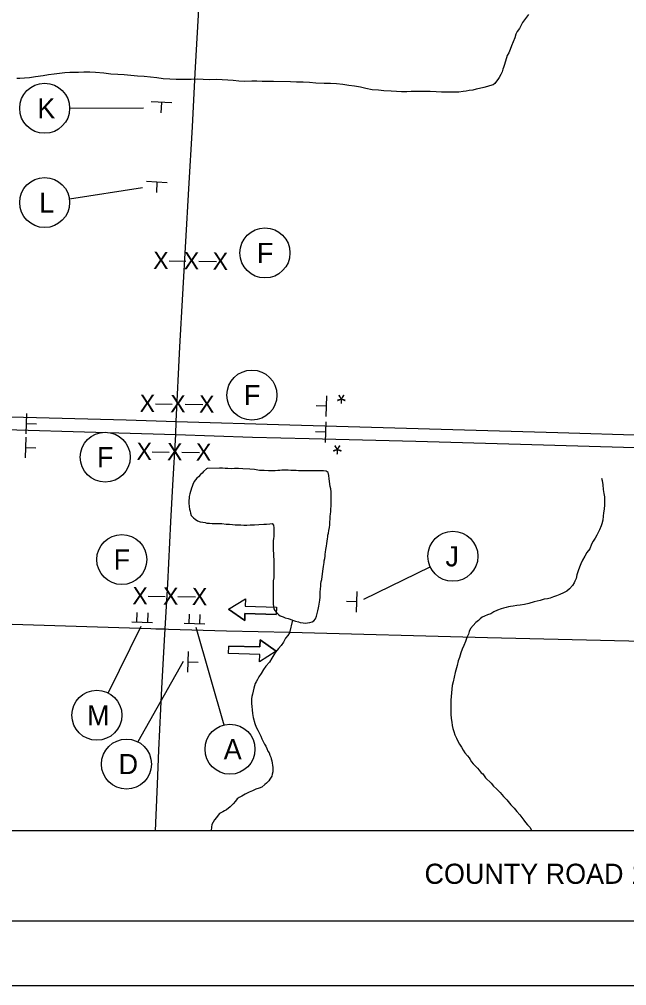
# Model space of a CAD drawing. Extents: x 1651.5 to 1685.5, y 1084.6 to 1106.6.
# Drawn here: x 1656.25 to 1660.95, y 1084.6 to 1092.09 of the extents above; entities that cross this region are included whole.
import ezdxf

# ---------------------------------------------------------------- set-up
doc = ezdxf.new("R2010")
doc.units = 0
for name, color, linetype in [('GM_X_County_Road', 7, 'Continuous'), ('GM_X_Minor_Lake', 7, 'Continuous'), ('GM_X_Minor_River', 7, 'Continuous'), ('GM_X_State_Route', 7, 'Continuous'), ('GM_X_Township_Road', 7, 'Continuous'), ('SC_Scratch1', 7, 'Continuous'), ('SH_Border', 7, 'Continuous'), ('SH_Data', 7, 'Continuous'), ('SH_Text', 7, 'Continuous'), ('SN_P_Signs', 7, 'Continuous'), ('SN_X_Public', 7, 'Continuous')]:
    doc.layers.add(name, color=color, linetype=linetype)

msp = doc.modelspace()

# ---------------------------------------------------------------- linework, layer by layer
at = {"layer": 'GM_X_County_Road'}
for points in [[(1657.4657, 1088.9713), (1657.4943, 1089.549), (1657.5621, 1090.7723), (1657.5909, 1091.2527), (1657.6123, 1091.6678), (1657.6464, 1092.2577), (1657.6502, 1092.3049), (1657.6569, 1092.3768), (1657.6601, 1092.4109)], [(1657.4608, 1088.8688), (1657.4657, 1088.9713)], [(1657.379, 1087.3642), (1657.3992, 1087.7139), (1657.4244, 1088.1945), (1657.439, 1088.4787), (1657.4608, 1088.8688)], [(1653.9882, 1087.4595), (1654.4044, 1087.4528), (1655.323, 1087.4263), (1656.1102, 1087.4042), (1657.2691, 1087.3668), (1657.3069, 1087.3659), (1657.379, 1087.3642)], [(1657.379, 1087.3642), (1657.4053, 1087.3633), (1657.8544, 1087.3482), (1658.3449, 1087.3387), (1659.8761, 1087.2977), (1661.0794, 1087.2696), (1662.2169, 1087.2377), (1663.5074, 1087.1976), (1664.3823, 1087.1736), (1664.5355, 1087.1696)]]:
    msp.add_lwpolyline(points, dxfattribs=at)
at = {"layer": 'GM_X_Minor_Lake'}
for points in [[(1657.7041, 1088.6067), (1657.7003, 1088.6046), (1657.6761, 1088.5832), (1657.6654, 1088.5699), (1657.652, 1088.5592), (1657.6386, 1088.5432), (1657.6252, 1088.5326), (1657.6037, 1088.5059), (1657.5929, 1088.4818), (1657.5876, 1088.4685), (1657.5822, 1088.4551), (1657.5714, 1088.4097), (1657.566, 1088.391), (1657.5659, 1088.3776), (1657.5632, 1088.3589), (1657.5632, 1088.3375), (1657.5658, 1088.3134), (1657.5684, 1088.292), (1657.5737, 1088.2759), (1657.5764, 1088.2598), (1657.5817, 1088.2437), (1657.5977, 1088.225), (1657.6111, 1088.2142), (1657.6298, 1088.2008), (1657.6511, 1088.1927), (1657.6725, 1088.19), (1657.6886, 1088.1872), (1657.702, 1088.1845), (1657.7234, 1088.1845), (1657.7448, 1088.1817), (1657.7689, 1088.1816), (1657.7929, 1088.1815), (1657.8197, 1088.1815), (1657.8518, 1088.176), (1657.8785, 1088.1759), (1657.8999, 1088.1732), (1657.9213, 1088.1704), (1657.9454, 1088.1704), (1657.9668, 1088.1703), (1657.9882, 1088.1675), (1658.0123, 1088.1675), (1658.0391, 1088.1701), (1658.0712, 1088.1699), (1658.106, 1088.1725), (1658.1434, 1088.1751), (1658.1649, 1088.175), (1658.1916, 1088.1776), (1658.2077, 1088.1802), (1658.2183, 1088.1668), (1658.221, 1088.1481), (1658.2209, 1088.132), (1658.2209, 1088.1106), (1658.2209, 1088.0972), (1658.2208, 1088.0812), (1658.2181, 1088.0651), (1658.2154, 1088.0464), (1658.2153, 1088.0277), (1658.2153, 1088.0143), (1658.2153, 1087.9983), (1658.2152, 1087.9822), (1658.2152, 1087.9688), (1658.2178, 1087.9501), (1658.2178, 1087.926), (1658.2204, 1087.9019), (1658.2204, 1087.8779), (1658.2203, 1087.8591), (1658.2203, 1087.8431), (1658.2202, 1087.8217), (1658.2202, 1087.8029), (1658.2201, 1087.7842), (1658.2201, 1087.7601), (1658.2173, 1087.7361), (1658.2173, 1087.712), (1658.2172, 1087.6879), (1658.2172, 1087.6692), (1658.2171, 1087.6505), (1658.2171, 1087.6291), (1658.2171, 1087.613), (1658.217, 1087.5969), (1658.217, 1087.5782), (1658.2169, 1087.5595), (1658.2196, 1087.5354), (1658.2222, 1087.5193), (1658.2302, 1087.5059), (1658.2409, 1087.4925), (1658.2569, 1087.4764), (1658.2703, 1087.4657), (1658.2943, 1087.4576), (1658.3103, 1087.4495), (1658.3317, 1087.4441), (1658.3478, 1087.4387), (1658.3665, 1087.4306), (1658.3879, 1087.4252), (1658.412, 1087.4197), (1658.4253, 1087.4143), (1658.4494, 1087.4116), (1658.4628, 1087.4089), (1658.4815, 1087.4115), (1658.5003, 1087.4141), (1658.519, 1087.4194)], [(1658.519, 1087.4194), (1658.5324, 1087.4274), (1658.5431, 1087.4434), (1658.5512, 1087.4621), (1658.5566, 1087.4835), (1658.562, 1087.5049), (1658.5674, 1087.5263), (1658.5701, 1087.5396), (1658.5728, 1087.5557), (1658.5782, 1087.5878), (1658.581, 1087.6092), (1658.581, 1087.6279), (1658.5811, 1087.6493), (1658.5838, 1087.6734), (1658.5865, 1087.6948), (1658.5866, 1087.7135), (1658.5893, 1087.7322), (1658.592, 1087.7456), (1658.5947, 1087.7697), (1658.6029, 1087.8285), (1658.6056, 1087.8472), (1658.6083, 1087.8632), (1658.611, 1087.8793), (1658.6111, 1087.8927), (1658.6164, 1087.9087), (1658.6192, 1087.9274), (1658.6192, 1087.9435), (1658.6219, 1087.9595), (1658.6246, 1087.9782), (1658.63, 1088.005), (1658.6328, 1088.0264), (1658.6355, 1088.0451), (1658.6382, 1088.0611), (1658.6409, 1088.0772), (1658.6409, 1088.0906), (1658.6437, 1088.1066), (1658.6464, 1088.1253), (1658.6518, 1088.1494), (1658.6545, 1088.1708), (1658.6545, 1088.1922), (1658.6573, 1088.2162), (1658.6573, 1088.2377), (1658.66, 1088.2537), (1658.6628, 1088.2724), (1658.6628, 1088.2938), (1658.6655, 1088.3152), (1658.6656, 1088.3366), (1658.6656, 1088.3553), (1658.6657, 1088.3741), (1658.6657, 1088.3928), (1658.6657, 1088.4089), (1658.6658, 1088.4249), (1658.6632, 1088.449), (1658.6579, 1088.4677), (1658.6552, 1088.4865), (1658.6526, 1088.5079), (1658.65, 1088.5266), (1658.6474, 1088.5534), (1658.6421, 1088.5748), (1658.626, 1088.5856), (1658.6073, 1088.5883), (1658.5859, 1088.5884), (1658.5725, 1088.5884), (1658.5565, 1088.5885), (1658.5324, 1088.5885), (1658.5163, 1088.5886), (1658.5029, 1088.5886), (1658.4869, 1088.5887), (1658.4735, 1088.5887), (1658.4601, 1088.5888), (1658.4441, 1088.5888), (1658.428, 1088.5889), (1658.412, 1088.5889), (1658.3932, 1088.5917), (1658.3745, 1088.5917), (1658.3531, 1088.5918), (1658.3317, 1088.5945), (1658.3023, 1088.5946), (1658.2835, 1088.5947), (1658.2675, 1088.5921), (1658.2514, 1088.5921), (1658.2327, 1088.5895), (1658.2086, 1088.5896), (1658.1792, 1088.5897), (1658.1471, 1088.5924), (1658.1096, 1088.5925), (1658.0722, 1088.598), (1658.0347, 1088.6008), (1657.9812, 1088.6037), (1657.9464, 1088.6065), (1657.917, 1088.6065), (1657.8902, 1088.604), (1657.8661, 1088.6067), (1657.8447, 1088.6068), (1657.8233, 1088.6095), (1657.7993, 1088.6096), (1657.7041, 1088.6067)]]:
    msp.add_lwpolyline(points, dxfattribs=at)
at = {"layer": 'GM_X_Minor_River'}
for points in [[(1660.1941, 1092.1229), (1660.1485, 1092.0615), (1660.1243, 1092.0161), (1660.1055, 1091.9921), (1660.0974, 1091.9707), (1660.0893, 1091.9439), (1660.0759, 1091.9119), (1660.0624, 1091.8798), (1660.0517, 1091.8531), (1660.0409, 1091.8264), (1660.0301, 1091.805), (1660.0086, 1091.7355), (1660.0005, 1091.7141), (1659.9951, 1091.7008), (1659.9897, 1091.6794), (1659.979, 1091.658), (1659.9682, 1091.6367), (1659.9575, 1091.6206), (1659.9467, 1091.6073), (1659.9333, 1091.5886), (1659.9199, 1091.5779), (1659.8931, 1091.57), (1659.8771, 1091.5647), (1659.8476, 1091.5568), (1659.8155, 1091.5515), (1659.7887, 1091.5463), (1659.762, 1091.5383), (1659.7352, 1091.5357), (1659.7111, 1091.5305), (1659.687, 1091.5279), (1659.6549, 1091.5226), (1659.6201, 1091.5227), (1659.5639, 1091.5229), (1659.5211, 1091.5231), (1659.4783, 1091.5232), (1659.4328, 1091.526), (1659.3953, 1091.5261), (1659.3579, 1091.5262), (1659.3231, 1091.5263), (1659.2856, 1091.5265), (1659.2508, 1091.5239), (1659.2107, 1091.524), (1659.1706, 1091.5268), (1659.1305, 1091.5296)], [(1659.1305, 1091.5296), (1659.0743, 1091.5325), (1659.0315, 1091.538), (1658.9833, 1091.5408), (1658.9352, 1091.549), (1658.8924, 1091.5598), (1658.8469, 1091.568), (1658.8014, 1091.5735), (1658.756, 1091.5817), (1658.7078, 1091.5872), (1658.6597, 1091.59), (1658.6115, 1091.5901), (1658.5473, 1091.5904), (1658.4965, 1091.5959), (1658.4483, 1091.5987), (1658.3975, 1091.5989), (1658.3493, 1091.6017), (1658.2182, 1091.6048), (1658.1754, 1091.6049), (1658.1299, 1091.6051), (1658.0898, 1091.6079), (1658.0496, 1091.608), (1657.9934, 1091.6055), (1657.9506, 1091.6083), (1657.9051, 1091.6111), (1657.865, 1091.6139), (1657.8222, 1091.6167), (1657.774, 1091.6196), (1657.7232, 1091.6171), (1657.6751, 1091.6199), (1657.6296, 1091.6227), (1657.5814, 1091.6202), (1657.5306, 1091.6203), (1657.4637, 1091.6206), (1657.4155, 1091.6234), (1657.3647, 1091.6262), (1657.3139, 1091.6317), (1657.2657, 1091.6372), (1657.2175, 1091.6428), (1657.164, 1091.6456), (1657.1132, 1091.6511), (1657.0624, 1091.6566), (1657.0115, 1091.6595), (1656.958, 1091.6623), (1656.9045, 1091.6678), (1656.8403, 1091.6734), (1656.7948, 1091.6762), (1656.7494, 1091.6764), (1656.7092, 1091.6738), (1656.6744, 1091.6739), (1656.6397, 1091.674), (1656.6022, 1091.6715), (1656.562, 1091.6663), (1656.5192, 1091.661), (1656.4764, 1091.6558), (1656.4336, 1091.6479), (1656.3747, 1091.6401), (1656.3292, 1091.6322), (1656.289, 1091.6297), (1656.2542, 1091.6271), (1656.2301, 1091.6272)], [(1660.7611, 1088.5306), (1660.7638, 1088.5145), (1660.769, 1088.4797), (1660.7717, 1088.4449), (1660.7769, 1088.4128), (1660.7822, 1088.3861), (1660.7821, 1088.3566), (1660.7821, 1088.3245), (1660.7793, 1088.2924), (1660.7766, 1088.263), (1660.7738, 1088.2363), (1660.7711, 1088.2068), (1660.763, 1088.1774), (1660.7576, 1088.1614), (1660.7442, 1088.132), (1660.7334, 1088.1106), (1660.7227, 1088.0893), (1660.7119, 1088.0679), (1660.6958, 1088.0439), (1660.6824, 1088.0198), (1660.6689, 1087.9851), (1660.6474, 1087.9557), (1660.6313, 1087.9264), (1660.6125, 1087.897), (1660.5991, 1087.8676), (1660.5883, 1087.8435), (1660.5802, 1087.8141), (1660.5695, 1087.7821), (1660.564, 1087.7553), (1660.5533, 1087.734), (1660.5479, 1087.7206), (1660.5345, 1087.6993), (1660.513, 1087.6752), (1660.4916, 1087.6566), (1660.4648, 1087.6433), (1660.438, 1087.63), (1660.4112, 1087.6194), (1660.3871, 1087.6114), (1660.363, 1087.6035), (1660.3416, 1087.5982), (1660.3148, 1087.5956), (1660.2854, 1087.585), (1660.2372, 1087.5745), (1660.197, 1087.5612), (1660.1622, 1087.5533), (1660.1301, 1087.548), (1660.1033, 1087.5455), (1660.0765, 1087.5402), (1660.0551, 1087.5376), (1660.0391, 1087.5349), (1660.0203, 1087.5297), (1660.0016, 1087.5244), (1659.9829, 1087.5191), (1659.9534, 1087.5085), (1659.9266, 1087.4952), (1659.9025, 1087.4819), (1659.8757, 1087.4739), (1659.8543, 1087.4633), (1659.8355, 1087.4553), (1659.8195, 1087.442), (1659.806, 1087.4287), (1659.7873, 1087.4127), (1659.7444, 1087.3673), (1659.7336, 1087.3433), (1659.7282, 1087.3246), (1659.7175, 1087.2979), (1659.7067, 1087.2658), (1659.6932, 1087.2364), (1659.6798, 1087.207), (1659.669, 1087.1776), (1659.6609, 1087.1429), (1659.6501, 1087.1161), (1659.642, 1087.0814), (1659.6258, 1087.0253), (1659.6177, 1086.9905), (1659.6096, 1086.9531), (1659.6042, 1086.9263), (1659.6015, 1086.8969), (1659.5987, 1086.8702), (1659.596, 1086.8407), (1659.5932, 1086.8113), (1659.5932, 1086.7739), (1659.5931, 1086.7391), (1659.593, 1086.7043), (1659.5956, 1086.6695), (1659.6009, 1086.6427), (1659.6035, 1086.616), (1659.6088, 1086.5919), (1659.6168, 1086.5705), (1659.6247, 1086.5437), (1659.6354, 1086.5169), (1659.646, 1086.4955), (1659.6594, 1086.4713), (1659.6754, 1086.4472), (1659.6887, 1086.4257), (1659.702, 1086.4043), (1659.7207, 1086.3802), (1659.734, 1086.3667), (1659.742, 1086.3533), (1659.7527, 1086.3346), (1659.766, 1086.3185)], [(1658.3665, 1087.4306), (1658.3422, 1087.3344), (1658.3288, 1087.313), (1658.3127, 1087.2916), (1658.2965, 1087.2623), (1658.2777, 1087.2356), (1658.2563, 1087.2116), (1658.2348, 1087.1849), (1658.2214, 1087.1635), (1658.2053, 1087.1368), (1658.1865, 1087.1074), (1658.1597, 1087.0754), (1658.1409, 1087.0487), (1658.1221, 1087.0193), (1658.1059, 1086.9926), (1658.0952, 1086.9713), (1658.0845, 1086.9553), (1658.0764, 1086.9419), (1658.071, 1086.9232), (1658.0656, 1086.9045), (1658.0602, 1086.8831), (1658.0548, 1086.859), (1658.0521, 1086.8403), (1658.0494, 1086.8216), (1658.0493, 1086.8055), (1658.0493, 1086.7868), (1658.0519, 1086.7627), (1658.0545, 1086.736), (1658.0571, 1086.7092), (1658.0624, 1086.6771), (1658.073, 1086.6316), (1658.0836, 1086.6021), (1658.097, 1086.5807), (1658.105, 1086.5646), (1658.1129, 1086.5485), (1658.1209, 1086.5324), (1658.1289, 1086.5137), (1658.1396, 1086.4922), (1658.1502, 1086.4708), (1658.1582, 1086.4547), (1658.1662, 1086.4386), (1658.1742, 1086.4172), (1658.1849, 1086.4038), (1658.1902, 1086.3851), (1658.1982, 1086.3716), (1658.2008, 1086.3583), (1658.2061, 1086.3422), (1658.214, 1086.2913), (1658.214, 1086.2753), (1658.214, 1086.2565), (1658.2086, 1086.2379), (1658.2059, 1086.2245), (1658.1898, 1086.2005), (1658.1817, 1086.1871), (1658.1656, 1086.1684), (1658.1522, 1086.1578), (1658.1281, 1086.1391), (1658.1066, 1086.1312), (1658.0825, 1086.1232), (1658.0558, 1086.1099), (1658.029, 1086.0993), (1657.9995, 1086.0833), (1657.9727, 1086.0674), (1657.954, 1086.0594), (1657.9379, 1086.0487), (1657.9245, 1086.0301), (1657.9057, 1086.0087), (1657.8842, 1085.9847), (1657.8547, 1085.9634), (1657.8387, 1085.9554), (1657.8253, 1085.9474), (1657.8012, 1085.9341), (1657.7904, 1085.9208), (1657.777, 1085.9021), (1657.7609, 1085.8861), (1657.7502, 1085.8674), (1657.7421, 1085.8487), (1657.7394, 1085.8273), (1657.7366, 1085.8033), (1657.7366, 1085.8005)], [(1659.766, 1086.3185), (1659.7794, 1086.3051), (1659.7981, 1086.2863), (1659.8114, 1086.2702), (1659.8274, 1086.2487), (1659.8408, 1086.2407), (1659.8515, 1086.2273), (1659.8621, 1086.2112), (1659.9048, 1086.1682), (1659.9235, 1086.1468), (1659.9475, 1086.1253), (1659.9742, 1086.0958), (1660.0009, 1086.0663), (1660.0276, 1086.0394), (1660.057, 1086.0019), (1660.0837, 1085.975), (1660.105, 1085.9509), (1660.1264, 1085.924), (1660.1424, 1085.9026), (1660.1584, 1085.8838), (1660.1717, 1085.865), (1660.1877, 1085.8463), (1660.2037, 1085.8275), (1660.2171, 1085.806), (1660.2219, 1085.8005)]]:
    msp.add_lwpolyline(points, dxfattribs=at)
at = {"layer": 'GM_X_State_Route'}
for points in [[(1653.9882, 1089.0716), (1654.5206, 1089.0563), (1655.2182, 1089.0358), (1655.7006, 1089.0196), (1656.1829, 1089.0075), (1657.0775, 1088.9829), (1657.4657, 1088.9713), (1658.3454, 1088.9451), (1660.4221, 1088.8844), (1661.0999, 1088.8659), (1661.6244, 1088.8494), (1662.2585, 1088.8312), (1663.3078, 1088.8007), (1664.1166, 1088.777), (1664.5833, 1088.7638), (1664.6413, 1088.7624), (1665.4938, 1088.737), (1665.9748, 1088.7239), (1666.6305, 1088.7038), (1667.0677, 1088.6901), (1668.268, 1088.6514), (1668.4116, 1088.6492), (1668.6882, 1088.6439)], [(1653.9882, 1088.972), (1654.9177, 1088.9448), (1655.9668, 1088.9137), (1656.6661, 1088.8935), (1657.4608, 1088.8688), (1658.0564, 1088.8506), (1658.4943, 1088.8393), (1659.3219, 1088.8187), (1660.1311, 1088.7948), (1661.7276, 1088.748), (1662.3619, 1088.7295), (1662.8212, 1088.7178), (1663.9585, 1088.6833), (1664.5805, 1088.6652), (1665.2488, 1088.6454), (1666.6484, 1088.6041), (1667.6764, 1088.5732), (1668.5696, 1088.5488), (1668.6882, 1088.5445)]]:
    msp.add_lwpolyline(points, dxfattribs=at)
at = {"layer": 'GM_X_Township_Road'}
msp.add_lwpolyline([(1657.3042, 1085.8005), (1657.3091, 1085.9224), (1657.3198, 1086.1627), (1657.3312, 1086.425), (1657.3548, 1086.9057), (1657.3765, 1087.3209), (1657.379, 1087.3642)], dxfattribs=at)
at = {"layer": 'SC_Scratch1'}
msp.add_lwpolyline([(1651.4632, 1106.6005), (1685.4632, 1106.6005), (1685.4632, 1084.6005), (1651.4632, 1084.6005)], close=True, dxfattribs=at)
at = {"layer": 'SH_Border'}
msp.add_lwpolyline([(1651.9632, 1106.1005), (1684.9632, 1106.1005), (1684.9632, 1085.1005), (1651.9632, 1085.1005)], close=True, dxfattribs=at)
at = {"layer": 'SH_Data'}
msp.add_lwpolyline([(1653.9882, 1105.4005), (1668.6882, 1105.4005), (1668.6882, 1085.8005), (1653.9882, 1085.8005)], close=True, dxfattribs=at)
at = {"layer": 'SH_Text'}
for p, q in [((1657.2122, 1091.3968), (1656.6394, 1091.3951)), ((1657.2037, 1090.7809), (1656.6375, 1090.6937)), ((1658.9175, 1087.595), (1659.4333, 1087.8443)), ((1657.8711, 1087.5165), (1658.0009, 1087.5976)), ((1658.0009, 1087.5976), (1657.9993, 1087.5406)), ((1657.8711, 1087.5165), (1657.9961, 1087.4281)), ((1657.9993, 1087.5406), (1658.2412, 1087.5337)), ((1658.2412, 1087.5337), (1658.2396, 1087.4758)), ((1657.9961, 1087.4281), (1657.9976, 1087.4826)), ((1657.9976, 1087.4826), (1658.2396, 1087.4758)), ((1657.1913, 1087.3817), (1656.9381, 1086.8678)), ((1657.6163, 1087.3781), (1657.8341, 1086.62)), ((1657.8699, 1087.1734), (1657.8715, 1087.2314)), ((1658.1135, 1087.2245), (1657.8715, 1087.2314)), ((1658.115, 1087.2791), (1658.1135, 1087.2245)), ((1658.2401, 1087.1907), (1658.115, 1087.2791)), ((1658.1118, 1087.1665), (1657.8699, 1087.1734)), ((1658.2401, 1087.1907), (1658.1102, 1087.1095)), ((1658.1102, 1087.1095), (1658.1118, 1087.1665)), ((1657.5179, 1087.1106), (1657.1671, 1086.49))]:
    msp.add_line(p, q, dxfattribs=at)
for points in [[(1658.2396, 1087.4758), (1657.9976, 1087.4826), (1657.9961, 1087.4281), (1657.8711, 1087.5165), (1658.0009, 1087.5976), (1657.9993, 1087.5406), (1658.2412, 1087.5337)], [(1657.8715, 1087.2314), (1658.1135, 1087.2245), (1658.115, 1087.2791), (1658.2401, 1087.1907), (1658.1102, 1087.1095), (1658.1118, 1087.1665), (1657.8699, 1087.1734)]]:
    msp.add_lwpolyline(points, close=True, dxfattribs=at)
msp.add_lwpolyline([(1657.379, 1087.3642), (1657.4053, 1087.3633), (1657.8544, 1087.3482), (1658.3449, 1087.3387), (1659.8761, 1087.2977), (1661.0794, 1087.2696), (1662.2169, 1087.2377), (1663.5074, 1087.1976), (1664.3823, 1087.1736), (1664.5355, 1087.1696)], dxfattribs=at)
for centre in [(1656.4458, 1091.3968), (1656.4458, 1090.6665), (1658.1527, 1090.2762), (1658.0519, 1089.1757), (1656.9154, 1088.6944), (1659.6086, 1087.9265), (1657.0435, 1087.9015), (1656.8506, 1086.6951), (1657.8817, 1086.4323), (1657.0796, 1086.3173)]:
    msp.add_circle(centre, 0.1936, dxfattribs=at)
at = {"layer": 'SN_P_Signs'}
for p, q in [((1657.4303, 1091.4383), (1657.2705, 1091.4466)), ((1657.3504, 1091.4425), (1657.3463, 1091.3626)), ((1657.3954, 1090.8203), (1657.2356, 1090.8286)), ((1657.3155, 1090.8244), (1657.3114, 1090.7445)), ((1657.4092, 1090.2149), (1657.5394, 1090.2132)), ((1657.6395, 1090.2119), (1657.7763, 1090.2101)), ((1657.3041, 1089.1078), (1657.4342, 1089.1061)), ((1657.5344, 1089.1047), (1657.6712, 1089.103)), ((1657.2795, 1088.736), (1657.4097, 1088.7343)), ((1657.5098, 1088.733), (1657.6466, 1088.7312)), ((1658.8627, 1087.4948), (1658.8675, 1087.6547)), ((1657.2481, 1087.6171), (1657.3782, 1087.6154)), ((1657.4784, 1087.6141), (1657.6152, 1087.6123)), ((1658.8651, 1087.5748), (1658.7851, 1087.5771)), ((1657.1606, 1087.4163), (1657.163, 1087.4916)), ((1657.2449, 1087.4136), (1657.2473, 1087.4889)), ((1657.5643, 1087.404), (1657.5667, 1087.4792)), ((1657.6486, 1087.4013), (1657.651, 1087.4765)), ((1657.2818, 1087.4124), (1657.1222, 1087.4175)), ((1657.6855, 1087.4001), (1657.5258, 1087.4052)), ((1657.5578, 1087.188), (1657.553, 1087.0281)), ((1657.5554, 1087.1081), (1657.6354, 1087.1057))]:
    msp.add_line(p, q, dxfattribs=at)
at = {"layer": 'SN_X_Public'}
for p, q in [((1658.6275, 1089.0094), (1658.6322, 1089.1693)), ((1658.6299, 1089.0893), (1658.5499, 1089.0917)), ((1656.3048, 1089.034), (1656.3002, 1088.8741)), ((1656.3025, 1088.9541), (1656.3825, 1088.9517)), ((1658.6217, 1088.8084), (1658.6263, 1088.9684)), ((1658.624, 1088.8884), (1658.544, 1088.8907)), ((1656.2995, 1088.8503), (1656.2948, 1088.6904)), ((1656.2972, 1088.7704), (1656.3771, 1088.768))]:
    msp.add_line(p, q, dxfattribs=at)

# ---------------------------------------------------------------- texts
at = {"layer": 'SH_Text'}
for s, p in [('K', (1656.3893, 1091.3188)), ('L', (1656.4034, 1090.5885)), ('F', (1658.0895, 1090.1982)), ('F', (1657.9887, 1089.0977)), ('F', (1656.8521, 1088.6164)), ('F', (1656.9802, 1087.8235)), ('J', (1659.5509, 1087.8485)), ('M', (1656.7744, 1086.6171)), ('A', (1657.8332, 1086.3543)), ('D', (1657.0188, 1086.2393)), ('COUNTY ROAD 180 DETOUR ROUTE', (1659.389, 1085.3894))]:
    msp.add_text(s, height=0.156, dxfattribs=at).set_placement(p)
for p in [(1658.7807, 1089.2478), (1658.7495, 1088.8569)]:
    msp.add_text('*', height=0.14, rotation=180, dxfattribs=at).set_placement(p)
at = {"layer": 'SN_P_Signs'}
for p in [(1657.2864, 1090.1529), (1657.5233, 1090.1498), (1657.7469, 1090.1469), (1657.1812, 1089.0458), (1657.4182, 1089.0427), (1657.6418, 1089.0398), (1657.1567, 1088.674), (1657.3936, 1088.6709), (1657.6172, 1088.668), (1657.1252, 1087.5552), (1657.3622, 1087.5521), (1657.5858, 1087.5492)]:
    msp.add_text('X', height=0.1333, rotation=359.25135, dxfattribs=at).set_placement(p)

doc.saveas('drawing.dxf')
